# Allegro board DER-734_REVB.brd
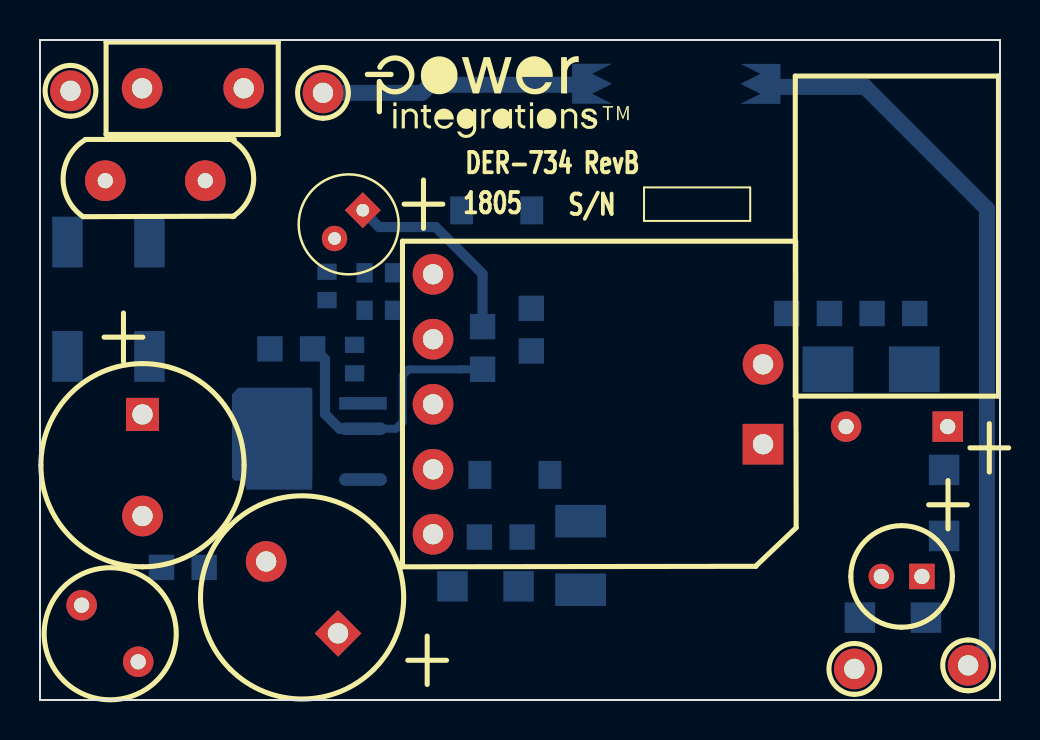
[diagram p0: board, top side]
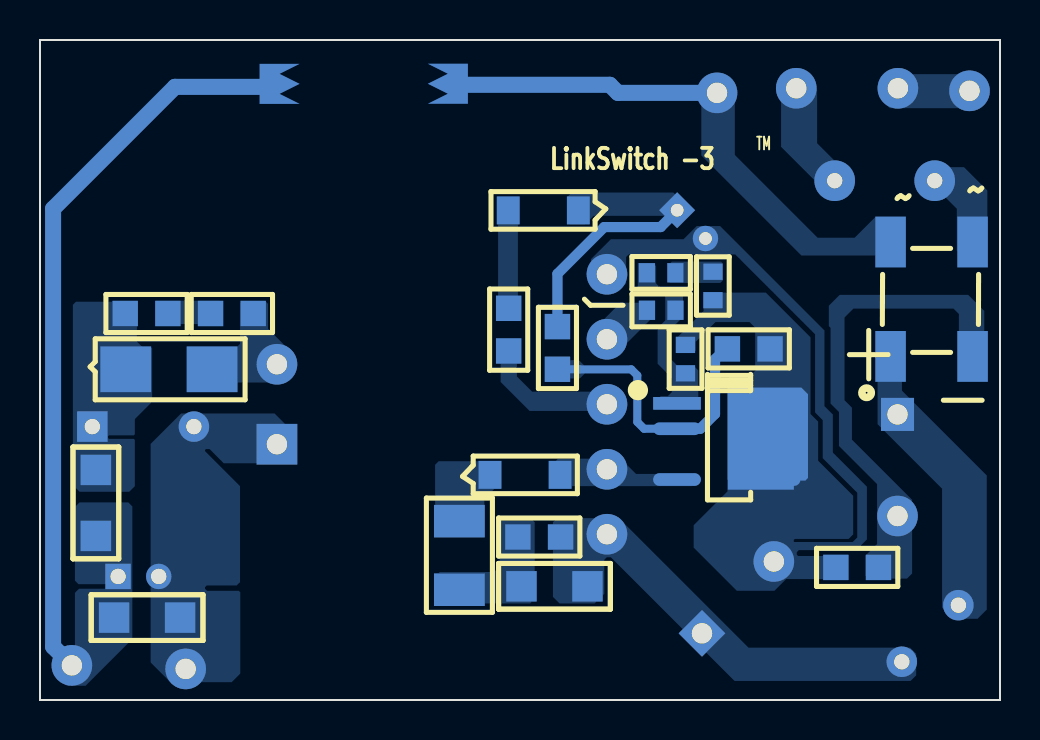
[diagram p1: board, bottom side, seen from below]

Outline 48 x 33 mm; copper layers: TOP, BOTTOM. Coordinates in mm from the lower left corner of the outline.
Outline path: 0,33 48,33 48,0 0,0 0,33

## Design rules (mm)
constraint set DEFAULT: min track width 0.508

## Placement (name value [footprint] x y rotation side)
BR1  LB10S  [PISMD_SOPA-4]  5.47 17.18 0 bottom
C1  10 uF  [PIPOLCAPCYLD400LS200040]  5.12 14.28 270 top
C2  10 uF  [PIPOLCAPCYLD400LS200040]  14.9 3.33 135 top
C3  680 uF  [PIPOLCAPCYLD400LS200040]  45.38 13.67 180 top
C4  10 uF  [PIPOLCAPCLYD5MMLS2MM025]  15.43 23.78 225 top
C5  1 uF  [PISMC0805]  13.63 17.56 180 bottom
C6  470 pF  [PISMC0805]  21.97 8.15 0 bottom
C7  1 nF  [PISMC0805]  41.61 19.32 0 bottom
C8  56 uF  [PIPOLCAPCLYD200LS80030]  44.1 6.18 180 top
C10  150 pF  [PISMC0603]  14.35 21.41 270 bottom
D1  MBRA2H100T3G  [PISMDO214AC12]  43.71 16.54 180 bottom
D2  UFM12PL-TP  [PI_SM_SOD-123_12]  21.08 24.48 0 bottom
D3  S1ML  [PI_SM_SOD-123_12]  25.5 11.26 180 bottom
F1  2 A  [PI_RST_MICROFUSE]  5.11 30.59 0 top
GND  BLK  [PITPKEYSTONE100X100]  40.72 1.55 0 top
L  WHT  [PITPKEYSTONE100X100]  1.53 30.46 0 top
L1  330 uH  [PICHOKETOKINVD276H413LS158D030]  2.08 4.74 315 top
L2  4.7 uH  [PISMR0805]  6.08 6.63 0 bottom
L3  Ferrite Bead (1.60 X 3.20 mm)  [PISMFERRITEBEAD1206]  45.21 11.51 270 bottom
N  BLK  [PITPKEYSTONE100X100]  14.15 30.36 0 top
NOREF  -  []  -228.6 -144.78 0 top
NOREF#2  -  []  0 0 0 top
NOREF#3  -  []  0 0 90 top
NOREF#4  -  []  16.26 32.66 0 top
NOREF#5  -  []  -150.78 54.23 0 top
R1  1.2  [PISMR0805]  24.57 17.45 90 bottom
R2  9.09 k  [PISMR0805]  22.13 16.54 90 bottom
R3  20.5 k  [PISMR0603]  17.65 19.49 180 bottom
R4  12.1 k  [PISMR0603]  15.73 16.33 90 bottom
R5  100  [PISMR1210]  27.03 5.51 90 bottom
R6  200 k  [PISMR1206]  20.63 5.69 0 bottom
R7  10  [PISMR0805]  37.34 19.32 0 bottom
R8  11 k  [PISMR1206]  44.3 4.12 180 bottom
R10  215 k  [PISMR0603]  17.65 21.36 180 bottom
RT1  2.5  [PI_RAD150X300LS200D030]  8.26 25.96 180 top
T1  EE16  [PI_BOBBIN_EE16_7P]  36.13 12.78 0 top
U1  LNK6407D  [PISMSO8DNSHORT5678]  16.15 14.83 270 bottom
UNK+12V  RED  [PITPKEYSTONE100X100]  46.41 1.73 0 top

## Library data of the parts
BR1 = DIODE BRIDGE_+~~-: alternate symbols: (pi_sm_soic4_slot)
C1 C2 C4 C8 = CAP POL
C3 = CAP POL: alternate symbols: (pipolcapclyd395x630ls200030h)
C5 C6 C10 = CAP NP
C7 = CAP NP: alternate symbols: (pismc0805_1)
D1 = DIODE SCHOTTKY
D2 D3 = DIODE
F1 = FUSE: alternate symbols: (pirstmicrofusehoz)
GND L N UNK+12V = TESTPOINT
L1 L2 = INDUCTOR
L3 = INDUCTOR_BEAD
R1-R8 R10 = R
RT1 = THERMISTOR: alternate symbols: (pirad400x300ls200040_h)
T1 = BEE16_7P_2
U1 = LNK6407

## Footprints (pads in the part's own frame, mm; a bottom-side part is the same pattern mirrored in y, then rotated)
PI_BOBBIN_EE16_7P
  rect 2.032x2.032 hole 1.016: 1(0.02,0.008)
  round 2.032 hole 1.016: 2(0.02,4.006) 3(-16.479,8.507) 4(-16.479,5.258) 5(-16.479,2.007) 6(-16.479,-1.245) 7(-16.479,-4.493)
PI_RAD150X300LS200D030
  round 2.032 hole 0.762: 1(0,0) 2(5,0)
PI_RST_MICROFUSE
  round 2.032 hole 1.016: 1(0,0) 2(5.08,0)
PI_SM_SOD-123_12
  rect 1.143x1.397 smd: 1(0,0) 2(3.505,0)
PICHOKETOKINVD276H413LS158D030
  round 1.524 hole 0.762: 1(0,0) 2(4,0)
PIPOLCAPCLYD5MMLS2MM025
  rect 1.27x1.27 hole 0.635: 1(-1,0)
  round 1.27 hole 0.635: 2(1,0)
PIPOLCAPCLYD200LS80030
  rect 1.27x1.27 hole 0.762: 1(0,0)
  round 1.27 hole 0.762: 2(2.032,0)
PIPOLCAPCYLD400LS200040
  rect 1.524x1.524 hole 0.762: 1(0,0)
  round 1.524 hole 0.762: 2(5.08,0)
PISMC0603
  rect 0.813x0.965 smd: 1(0,0) 2(1.422,0)
PISMC0805
  rect 1.27x1.27 smd: 1(0,0) 2(2.134,0)
PISMD_SOPA-4
  rect 1.524x2.54 smd: 1(0,0) 2(0,-5.72) 3(-4.1,-5.72) 4(-4.1,0)
PISMDO214AC12
  rect 2.54x2.286 smd: 1(0,0) 2(4.318,0)
PISMFERRITEBEAD1206
  rect 1.524x1.524 smd: 1(0,0) 2(3.302,0)
PISMR0603
  rect 0.813x0.965 smd: 1(0,0) 2(1.422,0)
PISMR0805
  rect 1.27x1.27 smd: 1(0,0) 2(2.134,0)
PISMR1206
  rect 1.524x1.524 smd: 1(0,0) 2(3.302,0)
PISMR1210
  rect 1.626x2.54 smd: 1(0,0) 2(3.429,0)
PISMSO8DNSHORT5678
  rect 0.635x2.388 smd: 1(0,0)
  oval 0.635x2.388 smd: 2(1.27,0) 4(3.81,0) 5(3.81,4.978) 6(2.54,4.978) 7(1.27,4.978) 8(0,4.978)
PITPKEYSTONE100X100
  round 2.032 hole 1.016: 1(0,0)

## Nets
S: C2.2 C4.2 C5.2 C10.2 L2.2 R4.2 T1.3 U1.5(S)
SOURCE: U1.6 U1.7 U1.8
N00231: BR1.3 RT1.2
N00241: BR1.2 N.1
N00354: BR1.1 C1.1 L1.1
N00466: C2.1 C6.1 L1.2 R6.1 T1.7
N00504: BR1.4 C1.2 L2.1
N01033: C5.1 R2.1 U1.2
N01924: C3.1 C7.2 D1.1 L3.1
N01931: C3.2 C8.2 GND.1 R8.2 T1.1
N02333: C4.1 D2.1 R2.2
N03183: R3.2 R4.1 R10.1 U1.1
N03289: R3.1 T1.4
N03434: D3.1 R5.2
N04514: D3.2 T1.6 U1.4
N04626: C6.2 R5.1 R6.2
N06055: C7.1 R7.2
N06246: D1.2 R7.1 T1.2
N06290: C8.1 L3.2 R8.1 UNK+12V.1
N12001: F1.2 RT1.1
N12005: F1.1 L.1
N16793: R1.1 T1.5
N016831: D2.2 R1.2
N21336: C10.1 R10.2

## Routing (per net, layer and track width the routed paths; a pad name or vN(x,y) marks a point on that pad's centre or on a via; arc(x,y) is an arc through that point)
N00241: length 13.2
  BOTTOM w0.8: 27.2,30.76 19.51,30.76 19.11,30.36 N.1
N01033: length 14.4
  BOTTOM w0.4: R2.1 21.04,16.54 21.03,16.53 18.44,16.53 18.14,16.23 18.14,13.9 17.8,13.56 U1.2
  BOTTOM w0.508: U1.2 14.99,13.56 14.25,14.3 14.25,17.04 13.73,17.56 C5.1
N02333: length 9.9
  BOTTOM w0.508: 16.16,24.46 16.97,23.65 19.79,23.65 22.13,21.31 R2.2
N06290: length 36.4
  BOTTOM w0.8: 36.65,30.66 41.25,30.66 47.35,24.56 47.35,2.67 UNK+12V.1

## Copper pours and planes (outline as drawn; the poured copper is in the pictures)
S on BOTTOM (solid shape): 13.61,10.51 10.31,10.51 10.31,15.34 13.61,15.34
S on BOTTOM (solid shape): 13.61,15.54 13.61,11.02 13.56,10.97 9.73,10.97 9.6,11.1 9.6,15.29 9.93,15.62 13.54,15.62
S on BOTTOM: 14,23.7 15.16,23.7 15.82,23.04 19.46,23.04 20.45,22.05 20.45,20.68 20.19,20.42 19.1,20.42 18.69,20.83 18.69,22.15 18.57,22.28 13.23,22.28 9.25,18.29 9.25,14.38 8.86,14 8.86,12.09 7.14,10.36 7.14,8.13 7.37,7.9 10.29,7.9 10.31,7.92 10.31,8 10.26,8.05 7.57,8.05 7.34,8.28 7.34,10.21 9.09,11.96 9.09,13.92 9.47,14.3 9.47,18.14 11.71,20.37 14.73,20.37 14.82,20.28 14.82,19.44 16.18,18.08 16.18,17.4 16.13,17.35 15.34,17.35 15.21,17.48 15.21,17.91 14.22,18.9 12.52,18.9 12.24,18.62 12.24,16.46 12.42,16.28 13.39,16.28 13.63,16.04 13.63,10.43 15.32,8.74 15.32,7.62 13.16,5.46 11.28,5.46 10.69,6.05 7.65,6.05 7.57,6.12 7.57,7.06 7.71,7.2 10.1,7.2 10.16,7.26 10.16,7.39 10.06,7.49 7.19,7.49 6.65,8.03 6.65,10.67 8.36,12.37 8.36,14.27 8.78,14.69 8.78,18.48
N00231 on BOTTOM: 1.93,22.23 0.76,22.23 0.64,22.35 0.64,25.48 1.8,26.64 3.58,26.64 3.78,26.44 3.78,25.58 3.4,25.2 2.79,25.2 2.16,24.56 2.16,22.45
N00241 on BOTTOM (solid shape): 27.61,31.31 28.61,30.81 27.61,30.31 28.61,29.81 26.61,29.81 26.61,31.81 28.61,31.81
N00241 on BOTTOM: 6.22,24.16 7.26,23.11 9.12,23.11 13.26,27.25 13.26,30.73 13.65,31.13 14.61,31.13 14.94,30.8 14.94,27.23 9.93,22.23 5.16,22.23 4.95,22.43 4.95,24.16
N00354 on BOTTOM: 4.98,18.44 4.9,18.36 4.9,15.47 0.66,11.23 0.66,4.52 1.12,4.06 2.34,4.06 2.9,4.62 2.9,10.57 6.12,13.79 6.12,18.44
N00466 on BOTTOM: 4.19,2.31 4.5,2.62 12.57,2.62 19.05,9.09 22.15,9.09 22.35,8.89 22.35,5.16 22.02,4.83 20.27,4.83 19.79,5.31 19.79,7.01 19.66,7.14 19.46,7.14 13.27,0.95 4.47,0.95 4.19,1.23
N00504 on BOTTOM: 8.01,20.26 8.56,19.71 8.56,14.83 8.09,14.36 8.09,12.74 6.15,10.79 6.15,7.8 6.73,7.21 6.73,6.22 6.58,6.07 4.65,6.07 4.39,6.32 4.39,10.01 7.4,13.02 7.4,14.62 7.77,14.99 7.77,19.13 7.33,19.57 2.32,19.57 2.06,19.3 2.06,16.36 1.96,16.26 0.81,16.26 0.79,16.28 0.79,19.46 1.59,20.26
N01033 on BOTTOM: 22.4,16.97 22.4,16.15 22.33,16.08 21.01,16.08 20.68,16.41 20.68,16.61 21.06,16.99 22.38,16.99
N01924 on BOTTOM: 43.26,14.05 43.26,13.28 43.31,13.23 44.55,13.23 44.6,13.18 44.6,13.11 44.55,13.06 43.31,13.06 43.26,13 43.26,10.69 43.54,10.41 46.02,10.41 46.35,10.74 46.35,19.76 46.2,19.91 43.38,19.91 43.15,19.68 43.15,17.92 42.9,17.67 42.48,17.67 42.39,17.58 42.39,14.91
N01931 on BOTTOM: 35.43,13.49 35.43,12.32 35.45,12.31 35.45,11.98 35.59,11.84 38.81,11.84 39.52,12.55 39.7,12.55 39.75,12.5 39.75,12.45 38,10.69 38,5.89 38.16,5.73 39.66,5.73 39.75,5.64 39.75,5.56 39.65,5.46 38.06,5.46 37.99,5.38 37.99,1.32 38.42,0.89 41.48,0.89 42.47,1.88 42.47,12.8 40.94,14.33 36.27,14.33
N02333 on BOTTOM: 20.75,23.77 20.32,24.21 16.81,24.21 16.46,23.85 16.03,23.85 15.49,24.38 15.49,24.54 16.33,25.37 21.41,25.37 21.59,25.2 21.59,23.88 21.49,23.77
N03183 on BOTTOM: 15.85,19.15 16.54,18.47 16.54,17.12 16.13,16.71 15.32,16.71 15.09,16.48 15.09,14.76 15.27,14.58 16.99,14.58 17.12,14.71 17.12,15.04 16.97,15.19 16.61,15.19 16.41,15.39 16.41,16.1 17.12,16.81 17.12,18.59 16.74,18.97 16.74,20.14 16.84,20.24 17.91,20.24 18.11,20.45 18.11,21.82 18.08,21.84 17.35,21.84 17.2,21.69 17.2,20.83 16.92,20.55 16,20.55 15.85,20.4
N03289 on BOTTOM: 17.45,19.81 17.45,19.05 19.25,17.25 20.04,17.25 20.42,17.63 20.42,18.41 18.97,19.86 17.5,19.86
N03434 on BOTTOM: 25.02,11.94 25.02,10.82 25.78,10.06 25.78,8.38 25.93,8.23 28.07,8.23 28.24,8.41 28.24,11.76 28.07,11.94
N04514 on BOTTOM: 22.1,12.06 22.4,11.76 22.4,10.87 22.23,10.69 15.39,10.69 15.21,10.87 15.21,11.15 15.37,11.3 18.2,11.3 18.96,12.06
N04626 on BOTTOM: 24.79,9.14 23.52,9.14 23.27,8.89 23.27,5.05 23.5,4.83 28.02,4.83 28.19,5 28.19,6.22 28.02,6.4 25.3,6.4 25.02,6.68 25.02,8.92
N06055 on BOTTOM: 38.99,19.91 38.99,18.85 39.04,18.8 42.06,18.8 42.21,18.95 42.21,19.96 39.04,19.96
N06246 on BOTTOM: 36.6,18.57 35.36,17.32 35.36,16.38 35.86,15.88 39.93,15.88 40.06,16 40.06,17.58 40.01,17.63 38.18,17.63 38,17.81 38,19.81 37.9,19.91 36.7,19.91 36.6,19.81
N06290 on BOTTOM (solid shape): 37.02,29.81 35.02,29.81 36.02,30.31 35.02,30.81 36.02,31.31 35.02,31.81 37.02,31.81
N06290 on BOTTOM: 45.72,0.71 46.66,0.71 47.07,1.12 47.07,1.93 46.25,2.74 46.25,5.36 46.05,5.56 44.68,5.56 44.63,5.61 44.63,5.74 44.68,5.79 46.08,5.79 46.25,5.97 46.25,9.65 46.02,9.88 43.59,9.88 43.38,9.68 43.38,3.05
N12001 on BOTTOM: 10.64,31.06 9.7,31.06 9.14,30.51 9.14,27.84 7.75,26.44 7.75,25.45 7.98,25.22 8.51,25.22 10.95,27.66 10.95,30.76
N12005 on BOTTOM: 0.81,31.06 0.81,29.95 1.17,29.59 5.51,29.59 5.89,29.97 5.89,30.99 5.59,31.29 1.04,31.29
N16793 on BOTTOM: 19.35,15.42 23.39,15.42 24.16,16.18 24.16,17.75 24.19,17.79 24.97,17.79 24.97,15.9 23.52,14.45 20.24,14.45 19.94,14.15 19.33,14.15 18.92,14.55 18.92,14.99
N016831 on BOTTOM: 24.1,19.13 24.1,24.94 24.23,25.07 24.89,25.07 25.1,24.87 25.1,19.13 24.92,18.95 24.28,18.95
N21336 on BOTTOM: 16.41,21.92 13.94,21.92 13.86,21.83 13.86,20.98 13.98,20.85 16.48,20.85 16.61,20.98 16.61,21.72

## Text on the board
Ref Des/Silkscreen Bottom: TM | LinkSwitch -3
Ref Des/Silkscreen Top: 1805 | DER-734 RevB | S/N
User.6: SLOT | 14.  FAB HOUSE LOGO,DATE CODE TO BE IN SILK SCREEN ONLY.DO NOT USE COPPER. | 13.  MATERIAL FR4 COPPER 1oz THICKNESS 0.039"
User.8: FIGURE | FINISHED_SIZE | 25.0 | 30.0 | 40.0 | DRILL CHART: TOP to BOTTOM | ALL UNITS ARE IN MILS | PLATED | QTY | 2 | 8 | 7 | 10
